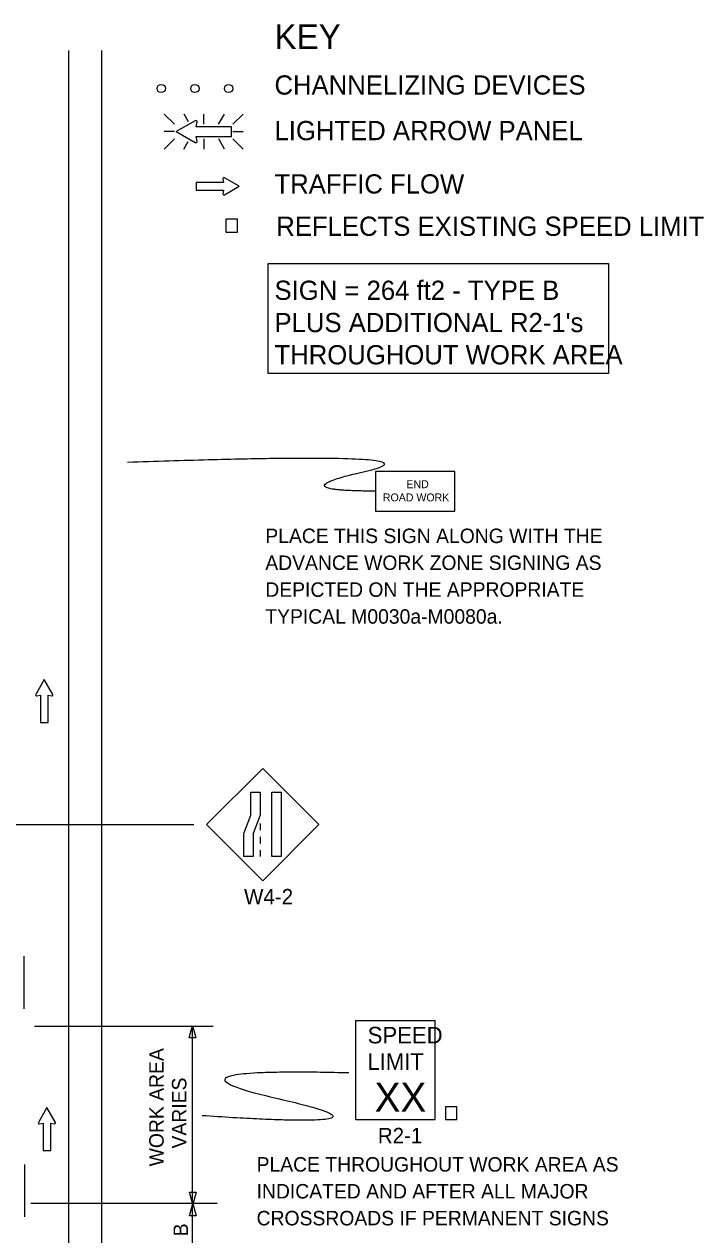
# Model space of a CAD drawing. Extents: x 16646 to 19498, y 2812 to 4437.
# Drawn here: x 17085 to 17414, y 3425 to 4011 of the extents above; entities that cross this region are included whole.
import ezdxf

# ---------------------------------------------------------------- set-up
doc = ezdxf.new("R2010")
doc.units = 0
for name, color, linetype in [('ALI_LEGAL_EX', 7, 'Continuous'), ('MT_SCRATCH_LEVEL_E', 7, 'Continuous'), ('PAVT_EDGE_EX', 7, 'Continuous'), ('TRAFFIC_SIGNS_PR', 7, 'Continuous'), ('TYPICAL_TEXT_DIMEN_EX', 7, 'Continuous'), ('TYPICAL_TEXT_DIMEN_PR', 7, 'Continuous')]:
    doc.layers.add(name, color=color, linetype=linetype)

msp = doc.modelspace()

# ---------------------------------------------------------------- linework, layer by layer
at = {"layer": 'ALI_LEGAL_EX'}
for points in [[(17085.13, 3534.8), (17085.13, 3560.32)], [(17085.41, 3434.11), (17085.41, 3459.51)]]:
    msp.add_lwpolyline(points, dxfattribs=at)
at = {"layer": 'MT_SCRATCH_LEVEL_E'}
for p, q in [((17181.34, 3936.36), (17181.65, 3934.59)), ((17181.34, 3936.36), (17181.65, 3934.59)), ((17189.26, 3932.74), (17182.02, 3936.85)), ((17189.26, 3932.74), (17182.02, 3936.85)), ((17181.65, 3934.59), (17168.4, 3934.59)), ((17168.4, 3934.59), (17168.4, 3930.85)), ((17181.65, 3934.59), (17168.4, 3934.59)), ((17168.4, 3934.59), (17168.4, 3930.85)), ((17168.4, 3930.85), (17181.65, 3930.85)), ((17168.4, 3930.85), (17181.65, 3930.85)), ((17181.65, 3930.85), (17181.34, 3929.07)), ((17181.65, 3930.85), (17181.34, 3929.07)), ((17182.02, 3928.59), (17189.26, 3932.74)), ((17182.02, 3928.59), (17189.26, 3932.74)), ((17094.78, 3694.1), (17090.67, 3686.86)), ((17094.78, 3694.1), (17090.67, 3686.86)), ((17098.92, 3686.86), (17094.78, 3694.1)), ((17098.92, 3686.86), (17094.78, 3694.1)), ((17091.15, 3686.18), (17092.93, 3686.49)), ((17091.15, 3686.18), (17092.93, 3686.49)), ((17092.93, 3686.49), (17092.93, 3673.23)), ((17092.93, 3686.49), (17092.93, 3673.23)), ((17096.67, 3673.23), (17096.67, 3686.49)), ((17096.67, 3686.49), (17098.45, 3686.18)), ((17096.67, 3673.23), (17096.67, 3686.49)), ((17096.67, 3686.49), (17098.45, 3686.18)), ((17092.93, 3673.23), (17096.67, 3673.23)), ((17092.93, 3673.23), (17096.67, 3673.23)), ((17096.07, 3487.05), (17091.96, 3479.81)), ((17096.07, 3487.05), (17091.96, 3479.81)), ((17100.21, 3479.81), (17096.07, 3487.05)), ((17100.21, 3479.81), (17096.07, 3487.05)), ((17092.44, 3479.12), (17094.22, 3479.44)), ((17092.44, 3479.12), (17094.22, 3479.44)), ((17094.22, 3479.44), (17094.22, 3466.18)), ((17094.22, 3479.44), (17094.22, 3466.18)), ((17097.96, 3466.18), (17097.96, 3479.44)), ((17097.96, 3479.44), (17099.74, 3479.12)), ((17097.96, 3466.18), (17097.96, 3479.44)), ((17097.96, 3479.44), (17099.74, 3479.12)), ((17094.22, 3466.18), (17097.96, 3466.18)), ((17094.22, 3466.18), (17097.96, 3466.18))]:
    msp.add_line(p, q, dxfattribs=at)
for centre, start, end in [((17181.8, 3936.44), 60.42484, 189.96381), ((17181.8, 3936.44), 60.42484, 189.96381), ((17181.8, 3929), 170.03619, 299.77312), ((17181.8, 3929), 170.03619, 299.77312), ((17091.07, 3686.63), 150.42484, 279.96381), ((17091.07, 3686.63), 150.42484, 279.96381), ((17098.52, 3686.64), 260.03619, 29.77312), ((17098.52, 3686.64), 260.03619, 29.77312), ((17092.36, 3479.58), 150.42484, 279.96381), ((17092.36, 3479.58), 150.42484, 279.96381), ((17099.8, 3479.58), 260.03619, 29.77312), ((17099.8, 3479.58), 260.03619, 29.77312)]:
    msp.add_arc(centre, 0.463, start, end, dxfattribs=at)
at = {"layer": 'PAVT_EDGE_EX'}
for p, q in [((17106.57, 3998.47), (17106.57, 3232.23)), ((17122.57, 3998.47), (17122.57, 3232.23))]:
    msp.add_line(p, q, dxfattribs=at)
at = {"layer": 'TRAFFIC_SIGNS_PR'}
for p, q in [((17152.95, 3967.67), (17157.88, 3962.74)), ((17164.71, 3963.85), (17162.5, 3967.68)), ((17172.03, 3962.74), (17172.03, 3967.68)), ((17179.26, 3962.74), (17182.11, 3967.68)), ((17186.18, 3962.74), (17191.11, 3967.68)), ((17157.88, 3959.18), (17152.95, 3959.18)), ((17152.95, 3950.7), (17157.88, 3955.63)), ((17162.46, 3950.69), (17164.57, 3954.36)), ((17172.03, 3955.63), (17172.03, 3950.69)), ((17182.16, 3950.69), (17179.31, 3955.63)), ((17186.18, 3959.18), (17191.11, 3959.18)), ((17186.18, 3955.63), (17191.11, 3950.69)), ((17200.59, 3651.07), (17173.44, 3623.92)), ((17227.74, 3623.92), (17200.59, 3651.07)), ((17173.44, 3623.92), (17200.59, 3596.76)), ((17199.34, 3624.41), (17199.34, 3621.21)), ((17200.59, 3596.76), (17227.74, 3623.92)), ((17199.34, 3618.01), (17199.34, 3614.81)), ((17199.34, 3611.61), (17199.34, 3608.41)), ((17245.66, 3529.19), (17284.06, 3529.19)), ((17245.66, 3481.19), (17245.66, 3529.19)), ((17284.06, 3481.19), (17284.06, 3529.19)), ((17245.66, 3481.19), (17284.06, 3481.19))]:
    msp.add_line(p, q, dxfattribs=at)
for points in [[(17167.96, 3964.46), (17158.67, 3959.18), (17167.96, 3953.86)], [(17168.83, 3954.49), (17168.43, 3956.76), (17185.44, 3956.76), (17185.44, 3961.56), (17168.43, 3961.56), (17168.83, 3963.84)]]:
    msp.add_lwpolyline(points, dxfattribs=at)
for points in [[(17182.78, 3910.57), (17188.37, 3910.57), (17188.37, 3916.75), (17182.78, 3916.75)], [(17255.18, 3775.54), (17293.58, 3775.54), (17293.58, 3794.74), (17255.18, 3794.74)], [(17199.34, 3639.65), (17199.34, 3628.47), (17196, 3619.59), (17196, 3608.41), (17191.51, 3608.41), (17191.51, 3619.59), (17194.85, 3628.47), (17194.85, 3639.65)], [(17209.48, 3639.65), (17209.48, 3608.41), (17204.99, 3608.41), (17204.99, 3639.65)], [(17289.08, 3481.19), (17294.67, 3481.19), (17294.67, 3487.36), (17289.08, 3487.36)]]:
    msp.add_lwpolyline(points, close=True, dxfattribs=at)
for centre in [(17151.46, 3980.03), (17167.76, 3980.03), (17184.06, 3980.03)]:
    msp.add_circle(centre, 2, dxfattribs=at)
for centre, radius, start, end in [((17168.25, 3963.94), 0.598, 350.73078, 118.89165), ((17168.24, 3954.39), 0.597, 241.48329, 9.95933)]:
    msp.add_arc(centre, radius, start, end, dxfattribs=at)
for points in [[(17255.34, 3785.25), (17208.1, 3785.25), (17293.12, 3804.6), (17135.16, 3799.11)], [(17242.3, 3503.76), (17142.32, 3506.3), (17275.17, 3476.08), (17171.29, 3483.05)]]:
    msp.add_open_spline(points, degree=2, dxfattribs=at)
at = {"layer": 'TYPICAL_TEXT_DIMEN_EX'}
msp.add_lwpolyline([(17203.31, 3895.33), (17368.03, 3895.33), (17368.03, 3842.1), (17203.31, 3842.1)], close=True, dxfattribs=at)
at = {"layer": 'TYPICAL_TEXT_DIMEN_PR'}
for p, q in [((17167.27, 3623.75), (17014.45, 3623.75)), ((17090.05, 3526.42), (17176.55, 3526.42)), ((17165, 3520.8), (17166.57, 3526.66)), ((17166.57, 3526.66), (17168.14, 3520.8)), ((17166.57, 3520.8), (17165, 3520.8)), ((17166.57, 3440.9), (17166.57, 3525.21)), ((17168.14, 3520.8), (17166.57, 3520.8)), ((17166.75, 3440.18), (17165.18, 3446.04)), ((17165.18, 3446.04), (17166.75, 3446.04)), ((17166.57, 3333.09), (17166.57, 3445.09)), ((17166.75, 3446.04), (17168.32, 3446.04)), ((17168.32, 3446.04), (17166.75, 3440.18)), ((17178.47, 3440.51), (17088.28, 3440.51)), ((17165.18, 3434.65), (17166.75, 3440.51)), ((17166.75, 3440.51), (17168.32, 3434.65)), ((17166.75, 3434.65), (17165.18, 3434.65)), ((17168.32, 3434.65), (17166.75, 3434.65))]:
    msp.add_line(p, q, dxfattribs=at)

# ---------------------------------------------------------------- texts
at = {"layer": 'TRAFFIC_SIGNS_PR'}
for s, height, p in [('END', 3.831, (17270.18, 3786.67)), ('ROAD WORK', 3.831, (17258.79, 3780.28)), ('PLACE THIS SIGN ALONG WITH THE', 7, (17201.85, 3760.1)), ('ADVANCE WORK ZONE SIGNING AS', 7, (17201.85, 3747.1)), ('DEPICTED ON THE APPROPRIATE', 7, (17201.85, 3734.1)), ('TYPICAL M0030a-M0080a.', 7, (17201.85, 3721.1)), ('W4-2', 7.44, (17191.55, 3585.32)), ('SPEED', 8, (17251.43, 3518.05)), ('LIMIT', 8, (17251.27, 3505.25)), ('XX', 14.031, (17254.78, 3484.95)), ('R2-1', 7.44, (17256.34, 3469.75)), ('PLACE THROUGHOUT WORK AREA AS', 7, (17197.64, 3456.01)), ('INDICATED AND AFTER ALL MAJOR', 7, (17197.64, 3443.01)), ('CROSSROADS IF PERMANENT SIGNS', 7, (17197.64, 3430.01))]:
    msp.add_text(s, height=height, dxfattribs=at).set_placement(p)
at = {"layer": 'TYPICAL_TEXT_DIMEN_EX'}
for s, height, p in [('KEY', 12, (17206.3, 3999.13)), ('CHANNELIZING DEVICES', 9.3, (17206.3, 3977.08)), ('LIGHTED ARROW PANEL', 9.3, (17206.3, 3955.03)), ('TRAFFIC FLOW', 9.3, (17206.3, 3929.23)), ('REFLECTS EXISTING SPEED LIMIT', 9.3, (17207.16, 3908.74)), ('SIGN = 264 ft2 - TYPE B', 9.3, (17206.3, 3877.76)), ("PLUS ADDITIONAL R2-1's", 9.3, (17206.3, 3862.16)), ('THROUGHOUT WORK AREA', 9.3, (17206.3, 3846.56))]:
    msp.add_text(s, height=height, dxfattribs=at).set_placement(p)
at = {"layer": 'TYPICAL_TEXT_DIMEN_PR'}
for s, p in [('WORK AREA', (17152.65, 3458.54)), ('VARIES', (17163.65, 3467.19)), ('B', (17164.42, 3424.72))]:
    msp.add_text(s, height=7, rotation=90, dxfattribs=at).set_placement(p)

doc.saveas('drawing.dxf')
